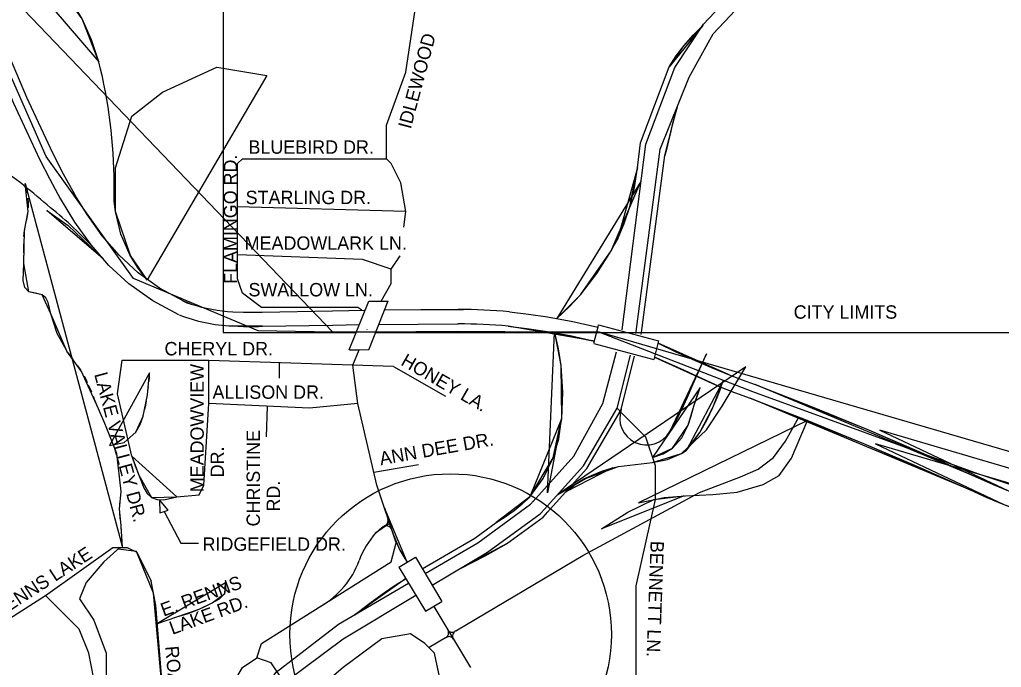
# Model space of a CAD drawing. Extents: x 5.01 to 9.58, y 0.27 to 3.39.
# Drawn here: x 7.24 to 8.037, y 0.644 to 1.17 of the extents above; entities that cross this region are included whole.
import ezdxf

# ---------------------------------------------------------------- set-up
doc = ezdxf.new("R2010")
doc.units = 0
for name, color, linetype in [('Level 7', 7, 'Continuous'), ('Level 9', 7, 'Continuous'), ('MO_001_NOSHOW', 7, 'Continuous'), ('MO_001_VIEW_PV', 7, 'Continuous')]:
    doc.layers.add(name, color=color, linetype=linetype)

msp = doc.modelspace()

# ---------------------------------------------------------------- linework, layer by layer
at = {"layer": 'Level 7'}
msp.add_circle((7.58964, 0.6707), 0.13045, dxfattribs=at)
at = {"layer": 'Level 9'}
for p, q in [((7.31992, 0.74003), (7.32131, 0.74131)), ((7.33477, 0.73797), (7.31992, 0.74003))]:
    msp.add_line(p, q, dxfattribs=at)
msp.add_lwpolyline([(7.32131, 0.74131), (7.30837, 0.72972), (7.29394, 0.71281), (7.28858, 0.6996), (7.30012, 0.68228), (7.31002, 0.65547), (7.31002, 0.63155), (7.2993, 0.61381), (7.296, 0.60432), (7.30054, 0.59607), (7.32446, 0.59565), (7.35834, 0.59707), (7.3486, 0.70427), (7.33477, 0.73797)], dxfattribs=at)
at = {"layer": 'MO_001_NOSHOW'}
for points in [[(7.30417, 1.13581), (7.2907, 1.17064), (7.25497, 1.21982), (7.2211, 1.24488), (7.1942, 1.26529), (7.16311, 1.30008)], [(7.49418, 0.91607), (7.43342, 0.91734), (7.3323, 0.9598), (7.26151, 1.05891), (7.22106, 1.14994), (7.18666, 1.23691)], [(7.76705, 1.13174), (7.77916, 1.14885), (7.79424, 1.16518)], [(7.3435, 0.95857), (7.32981, 0.97839), (7.31769, 1.01422), (7.3177, 1.04948), (7.33088, 1.09169), (7.35577, 1.111), (7.4, 1.13142), (7.44061, 1.12456)], [(7.7734, 1.09876), (7.76954, 1.08453), (7.7666, 1.07151), (7.7636, 1.05968)], [(7.72498, 0.99143), (7.73514, 1.01807), (7.74123, 1.0495)], [(7.32332, 0.74135), (7.32225, 0.75895), (7.32105, 0.7726), (7.32225, 0.78685), (7.31869, 0.81772), (7.30919, 0.84205), (7.30384, 0.85393), (7.2902, 0.8842), (7.27832, 0.90082), (7.26526, 0.93109), (7.25814, 0.94653), (7.24745, 0.94891), (7.24329, 0.97206), (7.24389, 0.99877), (7.24685, 1.01421), (7.24449, 1.03676)], [(7.67589, 0.92733), (7.69507, 0.94659), (7.71995, 0.98221), (7.74398, 1.03842)], [(7.26187, 1.01505), (7.27931, 1.00282), (7.30773, 0.97569)], [(7.37236, 0.94161), (7.37569, 0.9401), (7.37921, 0.93897)], [(7.41242, 0.92119), (7.43049, 0.9208), (7.43692, 0.92092)], [(7.49418, 0.91607), (7.59518, 0.91711), (7.71053, 0.91607)], [(7.63627, 0.921), (7.6665, 0.91705), (7.70642, 0.90898)], [(7.67387, 0.9158), (7.67899, 0.8891), (7.67971, 0.84566), (7.6682, 0.78563)], [(7.71053, 0.91607), (7.83478, 0.86807), (8.01737, 0.80132), (8.1234, 0.76598), (8.23138, 0.75027), (8.31974, 0.73653), (8.45325, 0.70708), (8.56909, 0.66584)], [(7.75808, 0.90725), (7.78568, 0.89419), (7.81571, 0.88148)], [(7.80764, 0.87203), (7.7788, 0.88518), (7.75524, 0.89589)], [(7.76747, 0.83545), (7.777, 0.8528), (7.78658, 0.87409), (7.79724, 0.89859)], [(7.67662, 0.78441), (7.69925, 0.79741), (7.72588, 0.80699), (7.75357, 0.8102), (7.777, 0.81765), (7.79724, 0.83682), (7.81002, 0.85599), (7.82919, 0.88795)], [(7.31275, 0.82424), (7.32463, 0.82662), (7.33412, 0.83493), (7.34006, 0.84799), (7.34362, 0.86521), (7.3454, 0.88302)], [(7.78106, 0.82028), (7.79191, 0.83469), (7.80257, 0.85493), (7.81108, 0.87729)], [(7.75362, 0.81452), (7.76973, 0.82202), (7.78255, 0.8406), (7.78703, 0.85598), (7.79215, 0.87136)], [(7.83678, 0.87357), (7.92881, 0.8368), (8.0178, 0.79788)], [(7.83269, 0.86261), (7.92473, 0.82585), (8.01371, 0.78692)], [(7.65403, 0.78236), (7.67288, 0.81406), (7.67971, 0.84566)], [(7.74214, 0.77749), (7.76292, 0.78187), (7.78039, 0.78337), (7.80233, 0.78437), (7.82229, 0.78636), (7.84324, 0.79235), (7.85621, 0.79983), (7.86618, 0.81381), (7.8794, 0.84438)], [(7.93803, 0.8367), (8.04229, 0.78726), (8.16026, 0.74513), (8.26909, 0.72407), (8.33669, 0.71913)], [(7.93442, 0.82557), (8.03868, 0.77613), (8.15665, 0.734), (8.26549, 0.71294), (8.33308, 0.708)], [(7.33104, 0.81538), (7.33675, 0.80002), (7.34693, 0.78202), (7.36755, 0.78237)], [(7.68328, 0.78661), (7.69211, 0.79368), (7.70393, 0.79989), (7.7211, 0.80588)], [(7.62665, 0.76151), (7.64113, 0.77146), (7.65403, 0.78236)], [(7.71224, 0.75655), (7.73354, 0.76993), (7.75462, 0.78035), (7.77913, 0.7833)], [(7.53605, 0.77339), (7.54311, 0.75222), (7.54824, 0.73979), (7.55445, 0.72933)], [(7.52892, 0.75325), (7.53502, 0.75826), (7.54004, 0.76082)], [(7.59758, 0.72426), (7.6176, 0.73455), (7.63506, 0.74442)], [(7.35174, 0.67952), (7.36745, 0.68491), (7.38557, 0.69118), (7.39613, 0.69646), (7.40635, 0.70404), (7.40702, 0.71261)], [(7.51186, 0.68668), (7.52512, 0.69701), (7.54306, 0.7097), (7.55314, 0.71599)]]:
    msp.add_lwpolyline(points, close=True, dxfattribs=at)
at = {"layer": 'MO_001_VIEW_PV'}
for p, q in [((7.40511, 1.58535), (7.40511, 0.91602)), ((7.41685, 0.97907), (7.41685, 1.01806)), ((7.55324, 1.01414), (7.41685, 1.01806)), ((7.55183, 1.00151), (7.55324, 1.01417)), ((7.54155, 0.96739), (7.54864, 0.97804)), ((7.50743, 0.90182), (7.52323, 0.94124)), ((7.52323, 0.90195), (7.53904, 0.94153)), ((7.43671, 0.93254), (7.49382, 0.93356)), ((7.43685, 0.92095), (7.49411, 0.92196)), ((7.52193, 0.91819), (7.52193, 0.91834)), ((7.70977, 0.92225), (7.75847, 0.90921)), ((7.40511, 0.91602), (7.51324, 0.91602)), ((7.52889, 0.91602), (8.12531, 0.91602)), ((7.75476, 0.894), (7.75854, 0.90913)), ((7.51034, 0.88949), (7.51541, 0.90195)), ((7.70586, 0.90704), (7.7547, 0.89399)), ((7.39337, 0.85818), (7.39337, 0.89326)), ((7.54338, 0.88834), (7.39337, 0.89326)), ((7.72817, 0.85366), (7.73892, 0.89669)), ((7.45062, 0.89138), (7.45062, 0.87891)), ((7.51425, 0.85818), (7.51034, 0.88949)), ((7.54338, 0.88834), (7.58541, 0.86413)), ((7.44033, 0.83123), (7.44119, 0.85601)), ((7.52744, 0.80253), (7.56353, 0.80876)), ((7.35713, 0.7705), (7.37076, 0.74485)), ((7.37076, 0.74485), (7.38511, 0.74485)), ((7.54773, 0.72528), (7.56107, 0.7334)), ((7.56107, 0.7334), (7.58266, 0.69744)), ((7.54773, 0.72528), (7.56932, 0.68948)), ((7.20625, 0.66731), (7.2609, 0.70238)), ((7.56932, 0.68948), (7.58266, 0.69744)), ((7.57599, 0.69353), (7.6057, 0.64397)), ((7.58563, 0.66798), (7.57233, 0.65999))]:
    msp.add_line(p, q, dxfattribs=at)
for points in [[(7.72882, 0.918), (7.74814, 1.06875), (7.77153, 1.13112), (7.79492, 1.1662), (7.85338, 1.22857), (8.05999, 1.42737)], [(7.73995, 0.9151), (7.74035, 0.91672), (7.75983, 1.06484), (7.78323, 1.12331), (7.80272, 1.1584), (7.86119, 1.22076), (8.07168, 1.42348)], [(7.53765, 1.05705), (7.53765, 1.08433), (7.55324, 1.12721), (7.56103, 1.1779), (7.56103, 1.23246), (7.55714, 1.25196), (7.55714, 1.27535), (7.56493, 1.29483), (7.57662, 1.30652), (7.61952, 1.32602), (7.61952, 1.34551)], [(7.30417, 1.13581), (7.29826, 1.15351), (7.2907, 1.17064), (7.27504, 1.19699), (7.26558, 1.20897), (7.25497, 1.21982), (7.23851, 1.23289), (7.2211, 1.24488), (7.20918, 1.25332), (7.19771, 1.26228)], [(7.76705, 1.13174), (7.77283, 1.14048), (7.77916, 1.14885), (7.78642, 1.15727), (7.79424, 1.16518)], [(7.27342, 1.02393), (7.26458, 1.04002), (7.25627, 1.05633), (7.2351, 1.10184), (7.21564, 1.1477), (7.21345, 1.15302), (7.21127, 1.15836)], [(7.2846, 1.02792), (7.27538, 1.04458), (7.26674, 1.06151), (7.24574, 1.10667), (7.22646, 1.15217), (7.22455, 1.15678), (7.22265, 1.16139)], [(7.74123, 1.0495), (7.74384, 1.06981), (7.76705, 1.13174)], [(7.7734, 1.09876), (7.77138, 1.09167), (7.76954, 1.08453), (7.76805, 1.07802), (7.7666, 1.07151), (7.76515, 1.06558), (7.7636, 1.05968)], [(7.74428, 0.91424), (7.74469, 0.91589), (7.7636, 1.05968)], [(7.4168, 1.01807), (7.4168, 1.05315), (7.42071, 1.05705), (7.53765, 1.05705)], [(7.55324, 1.01417), (7.54934, 1.03755), (7.54155, 1.05315), (7.53765, 1.05705)], [(7.72498, 0.99143), (7.7306, 1.00454), (7.73514, 1.01807), (7.7389, 1.03365), (7.74123, 1.0495)], [(7.24622, 1.02919), (7.24544, 1.03301), (7.24449, 1.03676)], [(7.3725, 0.94154), (7.35347, 0.95188), (7.33599, 0.96434), (7.32065, 0.97856), (7.30695, 0.99445), (7.29462, 1.01169), (7.28345, 1.02991)], [(7.34344, 0.95852), (7.33608, 0.96806), (7.32975, 0.97835), (7.32208, 0.99581), (7.31762, 1.01421), (7.31676, 1.02241), (7.31652, 1.03068)], [(7.2471, 1.01717), (7.24711, 1.02114), (7.24682, 1.02511)], [(7.36923, 0.93018), (7.34801, 0.9415), (7.32859, 0.95528), (7.31237, 0.97031), (7.29785, 0.98714), (7.28482, 1.00538), (7.27302, 1.02464)], [(7.24533, 1.00593), (7.24601, 1.0091), (7.2466, 1.01229)], [(7.24339, 0.99389), (7.24359, 0.99632), (7.24389, 0.99877), (7.24401, 0.99954), (7.24415, 1.00031)], [(7.2434, 0.98069), (7.24333, 0.98441), (7.24327, 0.98799)], [(7.67589, 0.92733), (7.6858, 0.93664), (7.69507, 0.94659), (7.70837, 0.96378), (7.71995, 0.98221), (7.72251, 0.9868), (7.72498, 0.99143)], [(7.27783, 0.90154), (7.27032, 0.91517), (7.26526, 0.93109), (7.26297, 0.94029), (7.26107, 0.94403), (7.25814, 0.94653), (7.25274, 0.94777), (7.24745, 0.94891), (7.24409, 0.95245), (7.24285, 0.95813), (7.24329, 0.97206), (7.24338, 0.97448), (7.24342, 0.97681)], [(7.51766, 0.93393), (7.51426, 0.93621), (7.43631, 0.93621), (7.42071, 0.94791), (7.4168, 0.9596), (7.4168, 0.97909)], [(7.54155, 0.96739), (7.51816, 0.97519), (7.4168, 0.97909)], [(7.53338, 0.94141), (7.54155, 0.9557), (7.54155, 0.96739)], [(7.37236, 0.94161), (7.374, 0.94081), (7.37569, 0.9401), (7.37743, 0.93948), (7.37921, 0.93897)], [(7.52328, 0.94127), (7.53114, 0.94137), (7.53897, 0.94147)], [(7.41301, 0.9328), (7.4217, 0.93248), (7.4304, 0.93242), (7.4335, 0.93246), (7.4366, 0.93253)], [(7.49385, 0.93353), (7.5071, 0.93377), (7.52037, 0.93398)], [(7.53606, 0.93419), (7.56561, 0.93446), (7.59516, 0.93457), (7.59764, 0.93458), (7.60012, 0.93458)], [(7.63744, 0.93264), (7.65293, 0.93085), (7.66837, 0.92859), (7.68886, 0.92487), (7.70919, 0.92034)], [(7.41242, 0.92119), (7.42146, 0.92088), (7.43049, 0.9208), (7.43371, 0.92085), (7.43692, 0.92092)], [(7.49407, 0.92191), (7.50486, 0.92211), (7.51566, 0.92229)], [(7.53137, 0.92244), (7.56326, 0.92275), (7.59517, 0.92288), (7.59552, 0.92288), (7.59588, 0.92288)], [(7.63627, 0.921), (7.65141, 0.91925), (7.6665, 0.91705), (7.68655, 0.91341), (7.70642, 0.90898)], [(7.70592, 0.9071), (7.70949, 0.92049), (7.70971, 0.92223)], [(7.67387, 0.9158), (7.67688, 0.90255), (7.67899, 0.8891), (7.6804, 0.86743), (7.67971, 0.84566)], [(7.5075, 0.90178), (7.51535, 0.90192), (7.5232, 0.90203)], [(7.75808, 0.90725), (7.77182, 0.90058), (7.78568, 0.89419), (7.80063, 0.88768), (7.81571, 0.88148)], [(7.2833, 0.89399), (7.28138, 0.89656), (7.27949, 0.89915)], [(7.33104, 0.81538), (7.31935, 0.86604), (7.32325, 0.89333), (7.39341, 0.89333)], [(7.65632, 0.7783), (7.68967, 0.81538), (7.71306, 0.85825), (7.72424, 0.90015)], [(7.66571, 0.77229), (7.69747, 0.80758), (7.72476, 0.85434), (7.73556, 0.89754)], [(7.80764, 0.87203), (7.79323, 0.87861), (7.7788, 0.88518), (7.76703, 0.89054), (7.75524, 0.89589)], [(7.29037, 0.88391), (7.29028, 0.88406), (7.2902, 0.8842), (7.28865, 0.88658), (7.28704, 0.88892)], [(7.29507, 0.87506), (7.29379, 0.87772), (7.29244, 0.88033)], [(7.34493, 0.87622), (7.34519, 0.87962), (7.3454, 0.88302)], [(7.76747, 0.83545), (7.7724, 0.84403), (7.777, 0.8528), (7.78193, 0.86338), (7.78658, 0.87409), (7.78795, 0.87724), (7.78933, 0.88039)], [(7.81571, 0.88148), (7.82623, 0.87752), (7.83678, 0.87357)], [(7.29838, 0.86743), (7.29717, 0.87032), (7.29593, 0.87319)], [(7.34361, 0.86519), (7.34362, 0.86521), (7.34362, 0.86521), (7.34407, 0.86852), (7.34448, 0.87184)], [(7.75362, 0.81452), (7.7621, 0.81739), (7.76973, 0.82202), (7.77735, 0.83042), (7.78255, 0.8406), (7.78495, 0.84826), (7.78703, 0.85598), (7.78947, 0.86371), (7.79215, 0.87136)], [(7.78106, 0.82028), (7.78675, 0.82729), (7.79191, 0.83469), (7.79762, 0.8446), (7.80257, 0.85493), (7.80603, 0.86313), (7.80915, 0.87146)], [(7.80766, 0.87203), (7.82017, 0.8673), (7.83269, 0.86261)], [(7.83678, 0.87357), (7.88295, 0.85556), (7.92881, 0.8368), (7.97346, 0.81769), (8.0178, 0.79788)], [(7.30171, 0.85911), (7.30073, 0.86155), (7.29977, 0.86399)], [(7.83269, 0.86261), (7.87886, 0.8446), (7.92473, 0.82585), (7.96813, 0.80728), (8.01123, 0.78806)], [(7.34149, 0.85348), (7.3422, 0.85677), (7.34281, 0.86009)], [(7.36755, 0.78237), (7.38562, 0.78418), (7.38951, 0.79198), (7.39341, 0.85825)], [(7.51426, 0.85825), (7.47527, 0.85434), (7.39341, 0.85825)], [(7.4324, 0.65165), (7.43631, 0.66334), (7.54155, 0.72962), (7.54545, 0.7452), (7.52986, 0.79198), (7.51426, 0.85825)], [(7.6681, 0.76974), (7.70029, 0.80551), (7.72801, 0.85303), (7.72817, 0.85366)], [(7.74035, 0.59707), (7.74035, 0.71012), (7.75593, 0.78028), (7.75593, 0.80758), (7.74814, 0.83096), (7.72866, 0.85045), (7.72476, 0.85434)], [(7.33359, 0.8342), (7.33386, 0.83457), (7.33412, 0.83493), (7.33762, 0.84121), (7.34006, 0.84799), (7.34017, 0.84838), (7.34028, 0.84876)], [(7.65403, 0.78236), (7.66477, 0.79741), (7.67288, 0.81406), (7.67746, 0.82963), (7.67971, 0.84566)], [(7.82489, 0.79869), (7.83926, 0.80488), (7.85166, 0.81452), (7.86153, 0.82761), (7.87213, 0.84722)], [(7.33104, 0.81538), (7.33373, 0.80776), (7.33675, 0.80002), (7.34072, 0.7897), (7.34338, 0.78526), (7.34693, 0.78202), (7.35153, 0.78035), (7.35686, 0.78007), (7.36755, 0.78237)], [(7.7211, 0.80588), (7.72348, 0.80648), (7.72588, 0.80699), (7.73963, 0.80877), (7.75357, 0.8102), (7.76571, 0.81283), (7.777, 0.81765), (7.77906, 0.81891), (7.78106, 0.82028)], [(7.68328, 0.78661), (7.68753, 0.79035), (7.69211, 0.79368), (7.69789, 0.79703), (7.70393, 0.79989), (7.71241, 0.80323), (7.7211, 0.80588)], [(7.59391, 0.67357), (7.69689, 0.73483), (7.79168, 0.78584), (7.82489, 0.79869)], [(8.0178, 0.79788), (8.03002, 0.79252), (8.04229, 0.78726), (8.1006, 0.76424), (8.16026, 0.74513), (8.21425, 0.73253), (8.26909, 0.72407), (8.30284, 0.72085), (8.33669, 0.71913)], [(7.62665, 0.76151), (7.63401, 0.76631), (7.64113, 0.77146), (7.64772, 0.77675), (7.65403, 0.78236)], [(8.01123, 0.78807), (8.02492, 0.78203), (8.03868, 0.77613), (8.09699, 0.75311), (8.15665, 0.734), (8.21065, 0.7214), (8.26549, 0.71294), (8.29923, 0.70972), (8.33308, 0.708)], [(7.32107, 0.77191), (7.32105, 0.77226), (7.32105, 0.7726), (7.32114, 0.77511), (7.32132, 0.77762)], [(7.53605, 0.77339), (7.53938, 0.76275), (7.54311, 0.75222), (7.54551, 0.74593), (7.54824, 0.73979), (7.55115, 0.73445), (7.55445, 0.72933)], [(7.56904, 0.72018), (7.61171, 0.7452), (7.65459, 0.77639), (7.65704, 0.77912)], [(7.3216, 0.76456), (7.32141, 0.76643), (7.32124, 0.76829)], [(7.57481, 0.71059), (7.61952, 0.73741), (7.66237, 0.76857), (7.66611, 0.77275)], [(7.63506, 0.74442), (7.66472, 0.76599), (7.66853, 0.77022)], [(7.32262, 0.75482), (7.32244, 0.75688), (7.32225, 0.75895), (7.3222, 0.75936), (7.32216, 0.75975)], [(7.52892, 0.75325), (7.53182, 0.75593), (7.53502, 0.75826), (7.53748, 0.75965), (7.54004, 0.76082)], [(7.5666, 0.72388), (7.60929, 0.7489), (7.62665, 0.76151)], [(7.32332, 0.74135), (7.32312, 0.74599), (7.32288, 0.75064)], [(7.26089, 0.70232), (7.31546, 0.74131), (7.32715, 0.74131), (7.33495, 0.73741), (7.34665, 0.71403)], [(7.59758, 0.72426), (7.60764, 0.72929), (7.6176, 0.73455), (7.62638, 0.73941), (7.63506, 0.74442)], [(7.35834, 0.59707), (7.35055, 0.69452), (7.34665, 0.71403)], [(7.35174, 0.67952), (7.35957, 0.68225), (7.36745, 0.68491), (7.37665, 0.68783), (7.38557, 0.69118), (7.39079, 0.69371), (7.39613, 0.69646), (7.40207, 0.69961), (7.40635, 0.70404), (7.40734, 0.7082), (7.40702, 0.71261)], [(7.37002, 0.49881), (7.4012, 0.57368), (7.448, 0.63996), (7.49866, 0.67894), (7.55558, 0.71231)], [(7.5121, 0.68687), (7.51844, 0.6919), (7.52512, 0.69701), (7.53399, 0.70349), (7.54306, 0.7097), (7.54807, 0.71289), (7.55314, 0.71599)], [(7.35834, 0.59707), (7.33884, 0.59318), (7.29596, 0.58928), (7.28817, 0.59707), (7.28817, 0.60876), (7.29986, 0.63606), (7.29596, 0.65555), (7.28817, 0.67504), (7.26089, 0.70232)], [(7.37882, 0.48797), (7.41291, 0.56979), (7.45579, 0.63217), (7.50256, 0.66725), (7.56143, 0.70257)], [(7.58832, 0.60097), (7.57662, 0.65555), (7.56883, 0.66334), (7.55714, 0.67113), (7.53376, 0.66725), (7.50256, 0.64386), (7.47527, 0.62048), (7.46358, 0.61656), (7.45189, 0.63606), (7.4441, 0.64775), (7.4324, 0.65165)], [(7.37393, 0.59707), (7.38562, 0.59318), (7.39341, 0.59707), (7.42071, 0.64386), (7.4324, 0.65165)]]:
    msp.add_lwpolyline(points, dxfattribs=at)
msp.add_lwpolyline([(7.35713, 0.7705), (7.36046, 0.77167), (7.35349, 0.78001), (7.3538, 0.76949)], close=True, dxfattribs=at)
for centre, radius, start, end in [((6.91177, 1.03643), 0.40479, 0, 14.21196), ((6.91177, 1.03643), 0.40479, 359.15948, 0.00001), ((7.07293, 0.77522), 0.30886, 42.3571, 51.55422), ((7.41905, 1.06166), 0.129, 252.01115, 267.29652), ((7.59637, 0.49826), 0.43631, 84.60887, 90.06632), ((7.41905, 1.06166), 0.14062, 249.30927, 267.29652), ((7.59637, 0.49826), 0.42462, 84.60887, 90.06632), ((7.74863, 0.8463), 0.02174, 160.22405, 330.03269), ((7.53747, 0.75431), 0.00464, 27.22345, 119.74446), ((7.53428, 0.76315), 0.00464, 293.98719, 0.00001), ((7.53428, 0.76315), 0.00464, 0, 15.90814), ((7.58194, 0.7063), 0.07082, 138.34541, 159.88791), ((7.44904, 0.75502), 0.07073, 300.04639, 339.85168), ((7.58338, 0.67203), 0.00464, 295.62428, 0.00001), ((7.58338, 0.67203), 0.00464, 0, 30.9594), ((7.59088, 0.67653), 0.00406, 210.96109, 305), ((7.59589, 0.66937), 0.00464, 115.17785, 212.5371), ((7.5884, 0.66487), 0.00406, 30.9611, 125)]:
    msp.add_arc(centre, radius, start, end, dxfattribs=at)
msp.add_ellipse((6.98218, 0.69985), major_axis=(-0.27584, 0.32555), ratio=0.995955, start_param=4.851704, end_param=4.985582, dxfattribs=at)

# ---------------------------------------------------------------- texts
for s, height, rotation, p in [('IDLEWOOD', 0.01087, 75, (7.5573, 1.08064)), ('FLAMINGO RD.', 0.0108704, 90, (7.41641, 0.95537)), ('HONEY LA.', 0.01087, 330, (7.54851, 0.8899)), ('MEADOWVIEW', 0.01087, 90, (7.38938, 0.78618)), ('LAKE VALLEY DR.', 0.0108703, 285, (7.30032, 0.88202)), ('CHRISTINE', 0.01087, 90, (7.43494, 0.75838)), ('ANN DEE DR.', 0.0108704, 10, (7.53296, 0.80805)), ('   DR.', 0.01087, 90, (7.40569, 0.78618)), ('   RD.', 0.01087, 90, (7.45124, 0.75838)), ('RENNS LAKE', 0.01087, 33, (7.22264, 0.6834)), ('BENNETT LN.', 0.0108704, 268, (7.75199, 0.74685)), ('E. RENNS', 0.01087, 20, (7.35672, 0.68508)), ('LAKE RD.', 0.01087, 20, (7.36382, 0.67031)), ('ROAD', 0.01087, 275, (7.35806, 0.66093))]:
    msp.add_text(s, height=height, rotation=rotation, dxfattribs=at).set_placement(p)
for s, height, p in [('BLUEBIRD DR.', 0.0108704, (7.42563, 1.06105)), ('STARLING DR.', 0.0108704, (7.42331, 1.02013)), ('MEADOWLARK LN.', 0.0108704, (7.42254, 0.98307)), ('SWALLOW LN.', 0.0108704, (7.42563, 0.94522)), ('CITY LIMITS', 0.0108704, (7.86806, 0.92709)), ('CHERYL DR.', 0.01087, (7.35748, 0.89732)), ('ALLISON DR.', 0.0108704, (7.39641, 0.86204)), ('RIDGEFIELD DR.', 0.0108704, (7.38837, 0.73861))]:
    msp.add_text(s, height=height, dxfattribs=at).set_placement(p)

doc.saveas('drawing.dxf')
